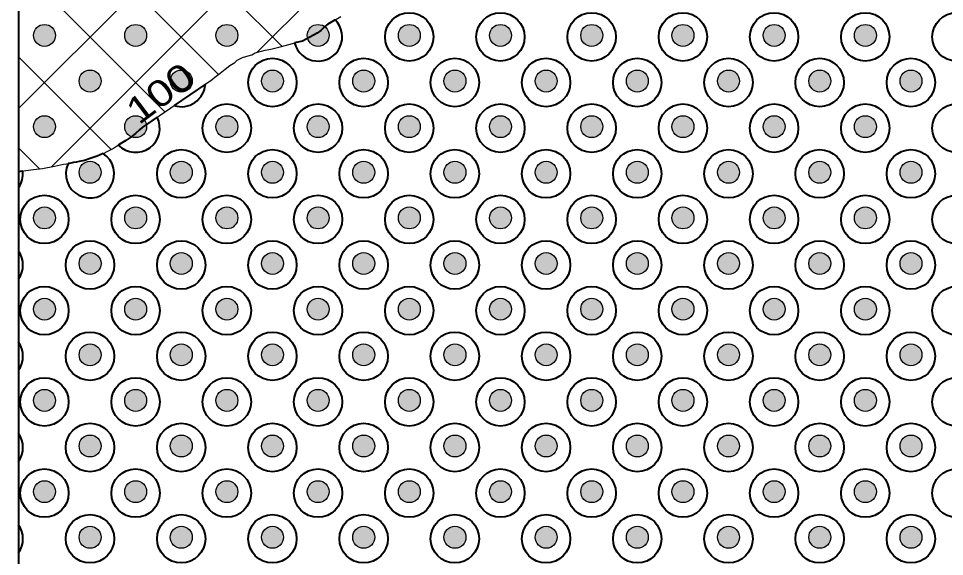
# Model space of a CAD drawing. Extents: x -10.5 to 30.8, y 18.4 to 58.7.
# Drawn here: x -10.13 to -2.95, y 25.07 to 29.24 of the extents above; entities that cross this region are included whole.
import ezdxf

# ---------------------------------------------------------------- set-up
doc = ezdxf.new("R2010")
doc.units = 0
doc.header["$LTSCALE"] = 0.08
for name, color, linetype, lineweight in [('10', 7, 'Continuous', 35), ('21', 7, 'Continuous', 25), ('22', 7, 'Continuous', 25), ('6', 7, 'Continuous', 40), ('60', 7, 'Continuous', 13), ('8', 7, 'Continuous', 25)]:
    doc.layers.add(name, color=color, linetype=linetype, lineweight=lineweight)

msp = doc.modelspace()

# ---------------------------------------------------------------- hatches: boundary and pattern name
at = {"layer": '22'}
for points in [[(-9.87169, 29.16988, 1), (-9.9919, 29.04967, 1)], [(-9.16458, 29.16988, 1), (-9.28479, 29.04967, 1)], [(-8.45747, 29.16988, 1), (-8.57768, 29.04967, 1)], [(-7.75037, 29.16988, 1), (-7.87058, 29.04967, 1)], [(-7.04326, 29.16988, 1), (-7.16347, 29.04967, 1)], [(-6.33615, 29.16988, 1), (-6.45636, 29.04967, 1)], [(-5.62905, 29.16988, 1), (-5.74925, 29.04967, 1)], [(-4.92194, 29.16988, 1), (-5.04215, 29.04967, 1)], [(-4.21483, 29.16988, 1), (-4.33504, 29.04967, 1)], [(-3.50773, 29.16988, 1), (-3.62793, 29.04967, 1)], [(-9.51813, 28.81632, 1), (-9.63834, 28.69611, 1)], [(-8.81103, 28.81632, 1), (-8.93124, 28.69611, 1)], [(-8.10392, 28.81632, 1), (-8.22413, 28.69611, 1)], [(-7.39681, 28.81632, 1), (-7.51702, 28.69611, 1)], [(-6.68971, 28.81632, 1), (-6.80992, 28.69611, 1)], [(-5.9826, 28.81632, 1), (-6.10281, 28.69611, 1)], [(-5.27549, 28.81632, 1), (-5.3957, 28.69611, 1)], [(-4.56839, 28.81632, 1), (-4.68859, 28.69611, 1)], [(-3.86128, 28.81632, 1), (-3.98149, 28.69611, 1)], [(-3.15417, 28.81632, 1), (-3.27438, 28.69611, 1)], [(-9.87169, 28.46277, 1), (-9.9919, 28.34256, 1)], [(-9.16458, 28.46277, 1), (-9.28479, 28.34256, 1)], [(-8.45747, 28.46277, 1), (-8.57768, 28.34256, 1)], [(-7.75037, 28.46277, 1), (-7.87058, 28.34256, 1)], [(-7.04326, 28.46277, 1), (-7.16347, 28.34256, 1)], [(-6.33615, 28.46277, 1), (-6.45636, 28.34256, 1)], [(-5.62905, 28.46277, 1), (-5.74925, 28.34256, 1)], [(-4.92194, 28.46277, 1), (-5.04215, 28.34256, 1)], [(-4.21483, 28.46277, 1), (-4.33504, 28.34256, 1)], [(-3.50773, 28.46277, 1), (-3.62793, 28.34256, 1)], [(-9.51813, 28.10922, 1), (-9.63834, 27.98901, 1)], [(-8.81103, 28.10922, 1), (-8.93124, 27.98901, 1)], [(-8.10392, 28.10922, 1), (-8.22413, 27.98901, 1)], [(-7.39681, 28.10922, 1), (-7.51702, 27.98901, 1)], [(-6.68971, 28.10922, 1), (-6.80992, 27.98901, 1)], [(-5.9826, 28.10922, 1), (-6.10281, 27.98901, 1)], [(-5.27549, 28.10922, 1), (-5.3957, 27.98901, 1)], [(-4.56839, 28.10922, 1), (-4.68859, 27.98901, 1)], [(-3.86128, 28.10922, 1), (-3.98149, 27.98901, 1)], [(-3.15417, 28.10922, 1), (-3.27438, 27.98901, 1)], [(-9.87169, 27.75566, 1), (-9.9919, 27.63545, 1)], [(-9.16458, 27.75566, 1), (-9.28479, 27.63545, 1)], [(-8.45747, 27.75566, 1), (-8.57768, 27.63545, 1)], [(-7.75037, 27.75566, 1), (-7.87058, 27.63545, 1)], [(-7.04326, 27.75566, 1), (-7.16347, 27.63545, 1)], [(-6.33615, 27.75566, 1), (-6.45636, 27.63545, 1)], [(-5.62905, 27.75566, 1), (-5.74925, 27.63545, 1)], [(-4.92194, 27.75566, 1), (-5.04215, 27.63545, 1)], [(-4.21483, 27.75566, 1), (-4.33504, 27.63545, 1)], [(-3.50773, 27.75566, 1), (-3.62793, 27.63545, 1)], [(-9.51813, 27.40211, 1), (-9.63834, 27.2819, 1)], [(-8.81103, 27.40211, 1), (-8.93124, 27.2819, 1)], [(-8.10392, 27.40211, 1), (-8.22413, 27.2819, 1)], [(-7.39681, 27.40211, 1), (-7.51702, 27.2819, 1)], [(-6.68971, 27.40211, 1), (-6.80992, 27.2819, 1)], [(-5.9826, 27.40211, 1), (-6.10281, 27.2819, 1)], [(-5.27549, 27.40211, 1), (-5.3957, 27.2819, 1)], [(-4.56839, 27.40211, 1), (-4.68859, 27.2819, 1)], [(-3.86128, 27.40211, 1), (-3.98149, 27.2819, 1)], [(-3.15417, 27.40211, 1), (-3.27438, 27.2819, 1)], [(-9.87169, 27.04856, 1), (-9.9919, 26.92835, 1)], [(-9.16458, 27.04856, 1), (-9.28479, 26.92835, 1)], [(-8.45747, 27.04856, 1), (-8.57768, 26.92835, 1)], [(-7.75037, 27.04856, 1), (-7.87058, 26.92835, 1)], [(-7.04326, 27.04856, 1), (-7.16347, 26.92835, 1)], [(-6.33615, 27.04856, 1), (-6.45636, 26.92835, 1)], [(-5.62905, 27.04856, 1), (-5.74925, 26.92835, 1)], [(-4.92194, 27.04856, 1), (-5.04215, 26.92835, 1)], [(-4.21483, 27.04856, 1), (-4.33504, 26.92835, 1)], [(-3.50773, 27.04856, 1), (-3.62793, 26.92835, 1)], [(-9.51813, 26.695, 1), (-9.63834, 26.57479, 1)], [(-8.81103, 26.695, 1), (-8.93124, 26.57479, 1)], [(-8.10392, 26.695, 1), (-8.22413, 26.57479, 1)], [(-7.39681, 26.695, 1), (-7.51702, 26.57479, 1)], [(-6.68971, 26.695, 1), (-6.80992, 26.57479, 1)], [(-5.9826, 26.695, 1), (-6.10281, 26.57479, 1)], [(-5.27549, 26.695, 1), (-5.3957, 26.57479, 1)], [(-4.56839, 26.695, 1), (-4.68859, 26.57479, 1)], [(-3.86128, 26.695, 1), (-3.98149, 26.57479, 1)], [(-3.15417, 26.695, 1), (-3.27438, 26.57479, 1)], [(-9.87169, 26.34145, 1), (-9.9919, 26.22124, 1)], [(-9.16458, 26.34145, 1), (-9.28479, 26.22124, 1)], [(-8.45747, 26.34145, 1), (-8.57768, 26.22124, 1)], [(-7.75037, 26.34145, 1), (-7.87058, 26.22124, 1)], [(-7.04326, 26.34145, 1), (-7.16347, 26.22124, 1)], [(-6.33615, 26.34145, 1), (-6.45636, 26.22124, 1)], [(-5.62905, 26.34145, 1), (-5.74925, 26.22124, 1)], [(-4.92194, 26.34145, 1), (-5.04215, 26.22124, 1)], [(-4.21483, 26.34145, 1), (-4.33504, 26.22124, 1)], [(-3.50773, 26.34145, 1), (-3.62793, 26.22124, 1)], [(-9.51813, 25.98789, 1), (-9.63834, 25.86769, 1)], [(-8.81103, 25.98789, 1), (-8.93124, 25.86769, 1)], [(-8.10392, 25.98789, 1), (-8.22413, 25.86769, 1)], [(-7.39681, 25.98789, 1), (-7.51702, 25.86769, 1)], [(-6.68971, 25.98789, 1), (-6.80992, 25.86769, 1)], [(-5.9826, 25.98789, 1), (-6.10281, 25.86769, 1)], [(-5.27549, 25.98789, 1), (-5.3957, 25.86769, 1)], [(-4.56839, 25.98789, 1), (-4.68859, 25.86769, 1)], [(-3.86128, 25.98789, 1), (-3.98149, 25.86769, 1)], [(-3.15417, 25.98789, 1), (-3.27438, 25.86769, 1)], [(-9.87169, 25.63434, 1), (-9.9919, 25.51413, 1)], [(-9.16458, 25.63434, 1), (-9.28479, 25.51413, 1)], [(-8.45747, 25.63434, 1), (-8.57768, 25.51413, 1)], [(-7.75037, 25.63434, 1), (-7.87058, 25.51413, 1)], [(-7.04326, 25.63434, 1), (-7.16347, 25.51413, 1)], [(-6.33615, 25.63434, 1), (-6.45636, 25.51413, 1)], [(-5.62905, 25.63434, 1), (-5.74925, 25.51413, 1)], [(-4.92194, 25.63434, 1), (-5.04215, 25.51413, 1)], [(-4.21483, 25.63434, 1), (-4.33504, 25.51413, 1)], [(-3.50773, 25.63434, 1), (-3.62793, 25.51413, 1)], [(-9.51813, 25.28079, 1), (-9.63834, 25.16058, 1)], [(-8.81103, 25.28079, 1), (-8.93124, 25.16058, 1)], [(-8.10392, 25.28079, 1), (-8.22413, 25.16058, 1)], [(-7.39681, 25.28079, 1), (-7.51702, 25.16058, 1)], [(-6.68971, 25.28079, 1), (-6.80992, 25.16058, 1)], [(-5.9826, 25.28079, 1), (-6.10281, 25.16058, 1)], [(-5.27549, 25.28079, 1), (-5.3957, 25.16058, 1)], [(-4.56839, 25.28079, 1), (-4.68859, 25.16058, 1)], [(-3.86128, 25.28079, 1), (-3.98149, 25.16058, 1)], [(-3.15417, 25.28079, 1), (-3.27438, 25.16058, 1)]]:
    msp.add_hatch(color=256, dxfattribs=at).paths.add_polyline_path(points)

# ---------------------------------------------------------------- linework, layer by layer
at = {"layer": '10'}
msp.add_lwpolyline([(-10.13304, 32.6247), (-10.13304, 32.32619), (-10.13304, 32.32619), (-10.13305, 22.04336), (-10.13305, 21.73), (-6.71324, 21.73)], dxfattribs=at)
at = {"layer": '21'}
for p, q in [((-8.28257, 28.97911), (-3.98737, 33.27431)), ((-10.13304, 28.54285), (-5.53116, 33.14473)), ((-9.87637, 28.09241), (-4.85333, 33.11545)), ((-8.09255, 29.02533), (-10.13304, 31.06583)), ((-8.58236, 28.80803), (-10.13304, 30.35872)), ((-8.99848, 28.51704), (-10.13304, 29.65161)), ((-9.41462, 28.22608), (-10.13304, 28.94451)), ((-9.97114, 28.0755), (-10.13304, 28.2374))]:
    msp.add_line(p, q, dxfattribs=at)
for points in [[(-9.75706, 32.75325), (-9.86116, 32.7183), (-9.86844, 32.71504), (-9.93329, 32.68908), (-10.03073, 32.66015), (-10.13305, 32.63719), (-10.13304, 32.32676), (-10.13304, 32.32619), (-10.13304, 32.32619), (-10.13304, 29.23739), (-10.13304, 28.05258)], [(-8.64688, 28.75687), (-8.64163, 28.76161), (-8.61175, 28.78692), (-8.56938, 28.81736), (-8.53202, 28.84775), (-8.49464, 28.87564), (-8.45723, 28.90102), (-8.43732, 28.91873), (-8.41734, 28.92893), (-8.39736, 28.93914), (-8.36984, 28.94691), (-8.32481, 28.95987), (-8.29735, 28.97515), (-8.21978, 28.99593), (-8.1772, 29.00386), (-8.10462, 29.02209), (-8.03705, 29.04027), (-7.9795, 29.05585), (-7.93193, 29.06632), (-7.81709, 29.1275), (-7.78967, 29.14778), (-7.75733, 29.17812), (-7.73491, 29.19585), (-7.70499, 29.21616), (-7.63511, 29.25688)], [(-10.13304, 28.05258), (-10.12035, 28.05404), (-10.07527, 28.06199), (-10.01766, 28.07006), (-9.9475, 28.07826), (-9.85486, 28.09669), (-9.78476, 28.1124), (-9.73714, 28.11787), (-9.70711, 28.12567), (-9.68707, 28.12837), (-9.66203, 28.13363), (-9.62197, 28.14153), (-9.57696, 28.15698), (-9.52444, 28.17501), (-9.47445, 28.19552), (-9.43949, 28.21338), (-9.40454, 28.23123), (-9.37461, 28.25154), (-9.33967, 28.2719), (-9.30225, 28.29479), (-9.26234, 28.3202), (-9.22498, 28.35059), (-9.19512, 28.3784), (-9.17472, 28.39683), (-8.64688, 28.75687)]]:
    msp.add_lwpolyline(points, dxfattribs=at)
at = {"layer": '22', "lineweight": 35}
msp.add_lwpolyline([(-9.79602, 31.41423), (-9.83585, 31.38132), (-9.88321, 31.34583), (-9.95306, 31.30261), (-9.99302, 31.2822), (-10.0155, 31.27197), (-10.04056, 31.26922), (-10.06815, 31.26895), (-10.09072, 31.26873), (-10.12085, 31.27093), (-10.13304, 31.27191), (-10.13305, 22.04336), (-10.13305, 21.73)], dxfattribs=at)
at = {"layer": '22'}
for centre in [(-9.93179, 29.10977), (-9.22468, 29.10977), (-8.51758, 29.10977), (-7.81047, 29.10977), (-7.10336, 29.10977), (-6.39626, 29.10977), (-5.68915, 29.10977), (-4.98204, 29.10977), (-4.27494, 29.10977), (-3.56783, 29.10977), (-9.57824, 28.75622), (-8.87113, 28.75622), (-8.16402, 28.75622), (-7.45692, 28.75622), (-6.74981, 28.75622), (-6.0427, 28.75622), (-5.3356, 28.75622), (-4.62849, 28.75622), (-3.92138, 28.75622), (-3.21428, 28.75622), (-9.93179, 28.40266), (-9.22468, 28.40266), (-8.51758, 28.40266), (-7.81047, 28.40266), (-7.10336, 28.40266), (-6.39626, 28.40266), (-5.68915, 28.40266), (-4.98204, 28.40266), (-4.27494, 28.40266), (-3.56783, 28.40266), (-9.57824, 28.04911), (-8.87113, 28.04911), (-8.16402, 28.04911), (-7.45692, 28.04911), (-6.74981, 28.04911), (-6.0427, 28.04911), (-5.3356, 28.04911), (-4.62849, 28.04911), (-3.92138, 28.04911), (-3.21428, 28.04911), (-9.93179, 27.69556), (-9.22468, 27.69556), (-8.51758, 27.69556), (-7.81047, 27.69556), (-7.10336, 27.69556), (-6.39626, 27.69556), (-5.68915, 27.69556), (-4.98204, 27.69556), (-4.27494, 27.69556), (-3.56783, 27.69556), (-9.57824, 27.342), (-8.87113, 27.342), (-8.16402, 27.342), (-7.45692, 27.342), (-6.74981, 27.342), (-6.0427, 27.342), (-5.3356, 27.342), (-4.62849, 27.342), (-3.92138, 27.342), (-3.21428, 27.342), (-9.93179, 26.98845), (-9.22468, 26.98845), (-8.51758, 26.98845), (-7.81047, 26.98845), (-7.10336, 26.98845), (-6.39626, 26.98845), (-5.68915, 26.98845), (-4.98204, 26.98845), (-4.27494, 26.98845), (-3.56783, 26.98845), (-9.57824, 26.6349), (-8.87113, 26.6349), (-8.16402, 26.6349), (-7.45692, 26.6349), (-6.74981, 26.6349), (-6.0427, 26.6349), (-5.3356, 26.6349), (-4.62849, 26.6349), (-3.92138, 26.6349), (-3.21428, 26.6349), (-9.93179, 26.28134), (-9.22468, 26.28134), (-8.51758, 26.28134), (-7.81047, 26.28134), (-7.10336, 26.28134), (-6.39626, 26.28134), (-5.68915, 26.28134), (-4.98204, 26.28134), (-4.27494, 26.28134), (-3.56783, 26.28134), (-9.57824, 25.92779), (-8.87113, 25.92779), (-8.16402, 25.92779), (-7.45692, 25.92779), (-6.74981, 25.92779), (-6.0427, 25.92779), (-5.3356, 25.92779), (-4.62849, 25.92779), (-3.92138, 25.92779), (-3.21428, 25.92779), (-9.93179, 25.57424), (-9.22468, 25.57424), (-8.51758, 25.57424), (-7.81047, 25.57424), (-7.10336, 25.57424), (-6.39626, 25.57424), (-5.68915, 25.57424), (-4.98204, 25.57424), (-4.27494, 25.57424), (-3.56783, 25.57424), (-9.57824, 25.22068), (-8.87113, 25.22068), (-8.16402, 25.22068), (-7.45692, 25.22068), (-6.74981, 25.22068), (-6.0427, 25.22068), (-5.3356, 25.22068), (-4.62849, 25.22068), (-3.92138, 25.22068), (-3.21428, 25.22068)]:
    msp.add_circle(centre, 0.085, dxfattribs=at)
at = {"layer": '6'}
for p, q in [((-8.6847, 28.73107), (-8.92729, 28.5656)), ((-10.13304, 27.43902), (-10.13304, 27.22191)), ((-10.13304, 26.73191), (-10.13304, 26.5148)), ((-10.13304, 26.02481), (-10.13304, 25.80769)), ((-10.13305, 25.3177), (-10.13305, 25.10059))]:
    msp.add_line(p, q, dxfattribs=at)
at = {"layer": '6', "lineweight": 25}
for points in [[(-8.64688, 28.75687), (-8.64163, 28.76161), (-8.61175, 28.78692), (-8.56938, 28.81736), (-8.53202, 28.84775), (-8.49464, 28.87564), (-8.45723, 28.90102), (-8.43732, 28.91873), (-8.41734, 28.92893), (-8.39736, 28.93914), (-8.36984, 28.94691), (-8.32481, 28.95987), (-8.29735, 28.97515), (-8.21978, 28.99593), (-8.1772, 29.00386), (-8.10462, 29.02209), (-8.03705, 29.04027), (-7.9795, 29.05585), (-7.93193, 29.06632), (-7.81709, 29.1275), (-7.78967, 29.14778), (-7.75733, 29.17812), (-7.73491, 29.19585), (-7.70499, 29.21616), (-7.63511, 29.25688)], [(-10.13304, 28.05258), (-10.12035, 28.05404), (-10.07527, 28.06199), (-10.01766, 28.07006), (-9.9475, 28.07826), (-9.85486, 28.09669), (-9.78476, 28.1124), (-9.73714, 28.11787), (-9.70711, 28.12567), (-9.68707, 28.12837), (-9.66203, 28.13363), (-9.62197, 28.14153), (-9.57696, 28.15698), (-9.52444, 28.17501), (-9.47445, 28.19552), (-9.43949, 28.21338), (-9.40454, 28.23123), (-9.37461, 28.25154), (-9.33967, 28.2719), (-9.30225, 28.29479), (-9.26234, 28.3202), (-9.22498, 28.35059), (-9.19512, 28.3784), (-9.17472, 28.39683), (-8.64688, 28.75687)], [(7.28557, 21.73), (-10.13305, 21.73), (-10.13304, 28.05258)]]:
    msp.add_lwpolyline(points, dxfattribs=at)
at = {"layer": '6'}
for points in [[(-7.67898, 29.23132), (-7.70499, 29.21616), (-7.73491, 29.19585), (-7.75733, 29.17812), (-7.78967, 29.14778), (-7.81709, 29.1275), (-7.93193, 29.06632), (-7.9795, 29.05585), (-7.99282, 29.05224)], [(-9.05822, 28.47629), (-9.17472, 28.39683), (-9.19512, 28.3784), (-9.22498, 28.35059), (-9.26234, 28.3202), (-9.30225, 28.29479), (-9.33967, 28.2719), (-9.35958, 28.2603)], [(-9.47649, 28.19468), (-9.52444, 28.17501), (-9.57696, 28.15698), (-9.62197, 28.14153), (-9.66203, 28.13363), (-9.68707, 28.12837), (-9.70711, 28.12567), (-9.73714, 28.11787), (-9.74888, 28.11652)], [(-10.09951, 28.05771), (-10.12035, 28.05404), (-10.13304, 28.05258), (-10.13304, 27.92901)]]:
    msp.add_lwpolyline(points, dxfattribs=at)
for centre in [(-7.10394, 29.09823), (-6.39684, 29.09823), (-5.68973, 29.09823), (-4.98262, 29.09823), (-4.27552, 29.09823), (-3.56841, 29.09823), (-2.8613, 29.09823), (-8.1646, 28.74468), (-7.4575, 28.74468), (-6.75039, 28.74468), (-6.04328, 28.74468), (-5.33618, 28.74468), (-4.62907, 28.74468), (-3.92196, 28.74468), (-3.21486, 28.74468), (-8.51816, 28.39112), (-7.81105, 28.39112), (-7.10394, 28.39112), (-6.39684, 28.39112), (-5.68973, 28.39112), (-4.98262, 28.39112), (-4.27552, 28.39112), (-3.56841, 28.39112), (-2.8613, 28.39112), (-8.87171, 28.03757), (-8.1646, 28.03757), (-7.4575, 28.03757), (-6.75039, 28.03757), (-6.04328, 28.03757), (-5.33618, 28.03757), (-4.62907, 28.03757), (-3.92196, 28.03757), (-3.21486, 28.03757), (-9.93237, 27.68402), (-9.22526, 27.68402), (-8.51816, 27.68402), (-7.81105, 27.68402), (-7.10394, 27.68402), (-6.39684, 27.68402), (-5.68973, 27.68402), (-4.98262, 27.68402), (-4.27552, 27.68402), (-3.56841, 27.68402), (-2.8613, 27.68402), (-9.57882, 27.33046), (-8.87171, 27.33046), (-8.1646, 27.33046), (-7.4575, 27.33046), (-6.75039, 27.33046), (-6.04328, 27.33046), (-5.33618, 27.33046), (-4.62907, 27.33046), (-3.92196, 27.33046), (-3.21486, 27.33046), (-9.93237, 26.97691), (-9.22526, 26.97691), (-8.51816, 26.97691), (-7.81105, 26.97691), (-7.10394, 26.97691), (-6.39684, 26.97691), (-5.68973, 26.97691), (-4.98262, 26.97691), (-4.27552, 26.97691), (-3.56841, 26.97691), (-2.8613, 26.97691), (-9.57882, 26.62336), (-8.87171, 26.62336), (-8.1646, 26.62336), (-7.4575, 26.62336), (-6.75039, 26.62336), (-6.04328, 26.62336), (-5.33618, 26.62336), (-4.62907, 26.62336), (-3.92196, 26.62336), (-3.21486, 26.62336), (-9.93237, 26.2698), (-9.22526, 26.2698), (-8.51816, 26.2698), (-7.81105, 26.2698), (-7.10394, 26.2698), (-6.39684, 26.2698), (-5.68973, 26.2698), (-4.98262, 26.2698), (-4.27552, 26.2698), (-3.56841, 26.2698), (-2.8613, 26.2698), (-9.57882, 25.91625), (-8.87171, 25.91625), (-8.1646, 25.91625), (-7.4575, 25.91625), (-6.75039, 25.91625), (-6.04328, 25.91625), (-5.33618, 25.91625), (-4.62907, 25.91625), (-3.92196, 25.91625), (-3.21486, 25.91625), (-9.93237, 25.5627), (-9.22526, 25.5627), (-8.51816, 25.5627), (-7.81105, 25.5627), (-7.10394, 25.5627), (-6.39684, 25.5627), (-5.68973, 25.5627), (-4.98262, 25.5627), (-4.27552, 25.5627), (-3.56841, 25.5627), (-2.8613, 25.5627), (-9.57882, 25.20914), (-8.87171, 25.20914), (-8.1646, 25.20914), (-7.4575, 25.20914), (-6.75039, 25.20914), (-6.04328, 25.20914), (-5.33618, 25.20914), (-4.62907, 25.20914), (-3.92196, 25.20914), (-3.21486, 25.20914)]:
    msp.add_circle(centre, 0.1875, dxfattribs=at)
for centre, start, end in [((-7.81105, 29.09823), 194.19813, 45.21963), ((-8.87171, 28.74468), 252.75767, 355.83789), ((-9.22526, 28.39112), 224.24442, 27.01572), ((-9.57882, 28.03757), 155.09786, 56.9238), ((-10.28592, 28.03757), 324.62197, 6.1671), ((-10.28592, 27.33046), 324.62194, 35.37805), ((-10.28592, 26.62336), 324.62192, 35.37808), ((-10.28592, 25.91625), 324.62189, 35.3781), ((-10.28592, 25.20914), 324.62187, 35.37812)]:
    msp.add_arc(centre, 0.1875, start, end, dxfattribs=at)
at = {"layer": '60', "lineweight": 40}
msp.add_line((-10.13304, 58.74412), (-10.13305, 21.73), dxfattribs=at)
at = {"layer": '8'}
for points in [[(-8.64688, 28.75687), (-8.64163, 28.76161), (-8.61175, 28.78692), (-8.56938, 28.81736), (-8.53202, 28.84775), (-8.49464, 28.87564), (-8.45723, 28.90102), (-8.43732, 28.91873), (-8.41734, 28.92893), (-8.39736, 28.93914), (-8.36984, 28.94691), (-8.32481, 28.95987), (-8.29735, 28.97515), (-8.21978, 28.99593), (-8.1772, 29.00386), (-8.10462, 29.02209), (-8.03705, 29.04027), (-7.9795, 29.05585), (-7.93193, 29.06632), (-7.81709, 29.1275), (-7.78967, 29.14778), (-7.75733, 29.17812), (-7.73491, 29.19585), (-7.70499, 29.21616), (-7.63511, 29.25688)], [(-10.13305, 28.05258), (-10.12035, 28.05404), (-10.07527, 28.06199), (-10.01766, 28.07006), (-9.9475, 28.07826), (-9.85486, 28.09669), (-9.78476, 28.1124), (-9.73714, 28.11787), (-9.70711, 28.12567), (-9.68707, 28.12837), (-9.66203, 28.13363), (-9.62197, 28.14153), (-9.57696, 28.15698), (-9.52444, 28.17501), (-9.47445, 28.19552), (-9.43949, 28.21338), (-9.40454, 28.23123), (-9.37461, 28.25154), (-9.33967, 28.2719), (-9.30225, 28.29479), (-9.26234, 28.3202), (-9.22498, 28.35059), (-9.19512, 28.3784), (-9.17472, 28.39683)]]:
    msp.add_lwpolyline(points, dxfattribs=at)

# ---------------------------------------------------------------- texts
at = {"layer": '8', "width": 1.25}
msp.add_text('100', height=0.2032, rotation=37, dxfattribs=at).set_placement((-9.20038, 28.411))

doc.saveas('drawing.dxf')
